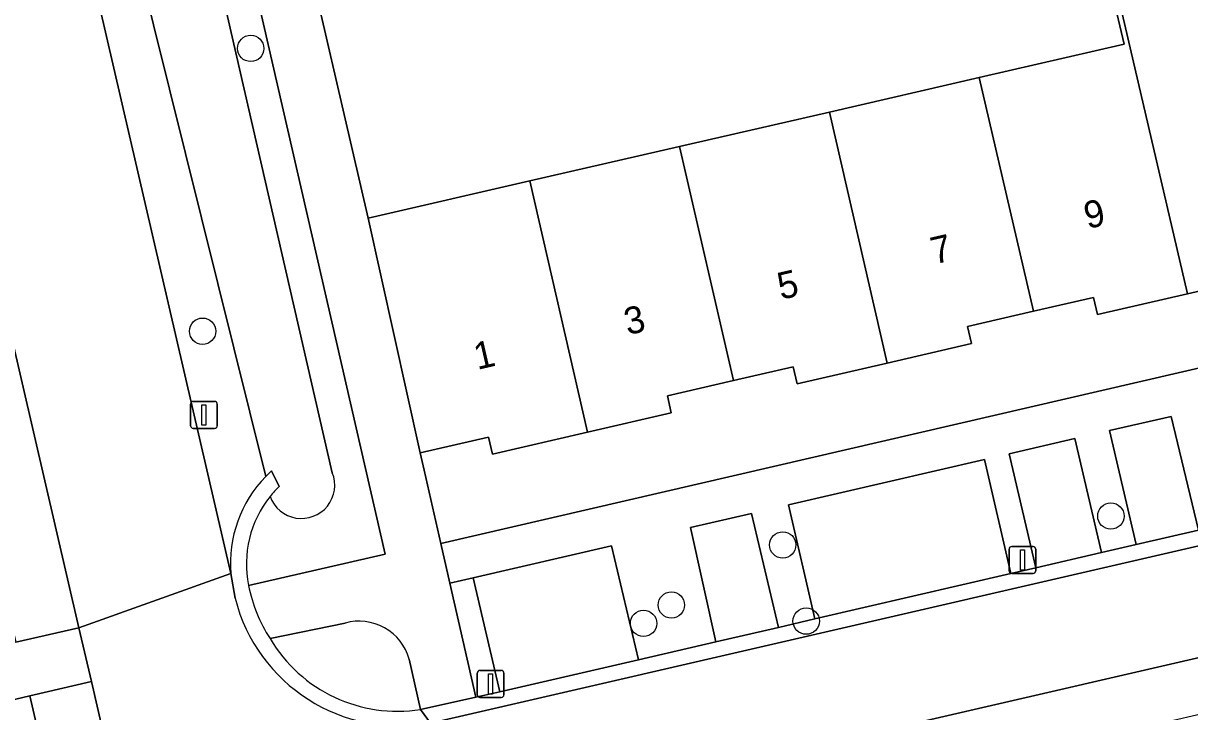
# Model space of a CAD drawing. Extents: x 156412 to 157779, y 382335 to 383768.
# Drawn here: x 156728.86 to 156772.11, y 382632.44 to 382657.96 of the extents above; entities that cross this region are included whole.
import ezdxf

# ---------------------------------------------------------------- set-up
doc = ezdxf.new("R2010")
doc.units = 0
for name, color, linetype in [('IMGEO_Berm_groen', 7, 'Continuous'), ('IMGEO_Boom', 7, 'Continuous'), ('IMGEO_Erf', 7, 'Continuous'), ('IMGEO_Greppel_droge_sloot', 7, 'Continuous'), ('IMGEO_Lichtmast', 7, 'Continuous'), ('IMGEO_Muur', 7, 'Continuous'), ('IMGEO_Pand', 7, 'Continuous'), ('IMGEO_Pand_nummerreeks', 7, 'Continuous'), ('IMGEO_Parkeervlak_halfverhard', 7, 'Continuous'), ('IMGEO_Parkeervlak_open', 7, 'Continuous'), ('IMGEO_Rijbaan_lokaal_gesloten', 7, 'Continuous'), ('IMGEO_Rijbaan_lokaal_open', 7, 'Continuous'), ('IMGEO_Voetpad_open', 7, 'Continuous')]:
    doc.layers.add(name, color=color, linetype=linetype)

msp = doc.modelspace()

# ---------------------------------------------------------------- linework, layer by layer
at = {"layer": 'IMGEO_Berm_groen'}
for points in [[(156737.216, 382637.122), (156742.279, 382638.288), (156737.212, 382660.364), (156736.732, 382660.236), (156734.423, 382669.916), (156734.988, 382670.057), (156729.8, 382692.978)], [(156725, 382688.405), (156725.228, 382687.423), (156725.004, 382687.432), (156736.553, 382637.563)], [(156729.729, 382687.434), (156740.319, 382641.302)], [(156737.852, 382641.163), (156726.53, 382686.636)], [(156740.791, 382635.724), (156738.015, 382635.156)], [(156743.594, 382632.529), (156743.168, 382634.389)]]:
    msp.add_lwpolyline(points, dxfattribs=at)
msp.add_lwpolyline([(156729.11, 382633.03), (156727.486, 382632.653), (156728.727, 382627.263), (156729.855, 382622.503), (156731.463, 382622.867)], close=True, dxfattribs=at)
for centre, radius, start, end in [((156739.176, 382640.838), 1.233, 199.5508, 22.1105), ((156741.202, 382637.92), 4.663, 135.9305, 184.3872), ((156741.125, 382637.925), 3.991, 141.2226, 191.6128), ((156741.32, 382633.882), 1.917, 15.3465, 106.0135), ((156742.728, 382637.928), 5.468, 210.4626, 279.1085)]:
    msp.add_arc(centre, radius, start, end, dxfattribs=at)
at = {"layer": 'IMGEO_Boom'}
for centre in [(156737.294, 382657.033), (156735.511, 382646.547), (156769.189, 382639.696), (156757.019, 382638.624), (156752.891, 382636.398), (156751.86, 382635.718), (156757.89, 382635.8)]:
    msp.add_circle(centre, 0.489, dxfattribs=at)
at = {"layer": 'IMGEO_Erf'}
for points in [[(156772.904, 382670.28), (156767.051, 382668.929), (156761.489, 382667.646), (156755.937, 382666.364), (156750.387, 382665.083), (156744.834, 382663.802), (156738.947, 382662.443), (156741.655, 382650.741), (156747.644, 382652.119), (156753.19, 382653.394), (156758.75, 382654.673), (156764.305, 382655.951), (156769.678, 382657.187), (156769.251, 382659.037), (156769.436, 382659.08), (156775.298, 382660.433)], [(156775.457, 382648.727), (156772.025, 382647.935), (156768.695, 382647.166), (156768.549, 382647.8), (156766.324, 382647.287), (156763.872, 382646.721), (156764.018, 382646.087), (156760.898, 382645.367), (156757.558, 382644.596), (156757.412, 382645.23), (156755.197, 382644.719), (156752.744, 382644.153), (156752.89, 382643.519), (156749.781, 382642.801), (156746.254, 382641.987), (156746.108, 382642.621), (156743.579, 382642.037), (156743.72, 382641.402), (156744.349, 382638.681), (156812.536, 382654.456)]]:
    msp.add_lwpolyline(points, dxfattribs=at)
at = {"layer": 'IMGEO_Greppel_droge_sloot'}
for points in [[(156740.319, 382641.302), (156729.729, 382687.434)], [(156726.53, 382686.636), (156737.852, 382641.163), (156738.07, 382641.375), (156738.348, 382640.791)]]:
    msp.add_lwpolyline(points, dxfattribs=at)
for centre, radius, start, end in [((156739.176, 382640.838), 1.233, 199.5508, 22.1105), ((156741.083, 382637.959), 3.937, 134.0097, 141.2251)]:
    msp.add_arc(centre, radius, start, end, dxfattribs=at)
at = {"layer": 'IMGEO_Lichtmast'}
for p, q in [((156735.165, 382643.946), (156735.955, 382643.946)), ((156735.955, 382643.946), (156735.165, 382643.946)), ((156735.065, 382643.046), (156735.065, 382643.846)), ((156735.065, 382643.846), (156735.065, 382643.046)), ((156736.055, 382643.846), (156736.055, 382643.046)), ((156736.055, 382643.046), (156736.055, 382643.846)), ((156735.955, 382642.946), (156735.165, 382642.946)), ((156735.165, 382642.946), (156735.955, 382642.946)), ((156765.412, 382637.667), (156765.412, 382638.467)), ((156765.412, 382638.467), (156765.412, 382637.667)), ((156765.512, 382638.567), (156766.302, 382638.567)), ((156766.302, 382638.567), (156765.512, 382638.567)), ((156766.402, 382638.467), (156766.402, 382637.667)), ((156766.402, 382637.667), (156766.402, 382638.467)), ((156766.302, 382637.567), (156765.512, 382637.567)), ((156765.512, 382637.567), (156766.302, 382637.567)), ((156745.795, 382633.972), (156746.585, 382633.972)), ((156746.585, 382633.972), (156745.795, 382633.972)), ((156745.695, 382633.072), (156745.695, 382633.872)), ((156745.695, 382633.872), (156745.695, 382633.072)), ((156746.685, 382633.872), (156746.685, 382633.072)), ((156746.685, 382633.072), (156746.685, 382633.872)), ((156746.585, 382632.972), (156745.795, 382632.972)), ((156745.795, 382632.972), (156746.585, 382632.972))]:
    msp.add_line(p, q, dxfattribs=at)
for points in [[(156735.485, 382643.821), (156735.635, 382643.821), (156735.635, 382643.071), (156735.485, 382643.071), (156735.485, 382643.821)], [(156765.832, 382638.442), (156765.982, 382638.442), (156765.982, 382637.692), (156765.832, 382637.692), (156765.832, 382638.442)], [(156746.115, 382633.847), (156746.265, 382633.847), (156746.265, 382633.097), (156746.115, 382633.097), (156746.115, 382633.847)]]:
    msp.add_lwpolyline(points, dxfattribs=at)
for centre, start, end in [((156735.165, 382643.846), 90, 180), ((156735.165, 382643.846), 90, 180), ((156735.955, 382643.846), 0, 90), ((156735.955, 382643.846), 360, 90), ((156735.165, 382643.046), 180, 270), ((156735.165, 382643.046), 180, 270), ((156735.955, 382643.046), 270, 0), ((156735.955, 382643.046), 270, 0), ((156765.512, 382638.467), 90, 180), ((156765.512, 382638.467), 90, 180), ((156766.302, 382638.467), 0, 90), ((156766.302, 382638.467), 360, 90), ((156765.512, 382637.667), 180, 270), ((156765.512, 382637.667), 180, 270), ((156766.302, 382637.667), 270, 0), ((156766.302, 382637.667), 270, 0), ((156745.795, 382633.872), 90, 180), ((156745.795, 382633.872), 90, 180), ((156746.585, 382633.872), 0, 90), ((156746.585, 382633.872), 360, 90), ((156745.795, 382633.072), 180, 270), ((156745.795, 382633.072), 180, 270), ((156746.585, 382633.072), 270, 0), ((156746.585, 382633.072), 270, 0)]:
    msp.add_arc(centre, 0.1, start, end, dxfattribs=at)
at = {"layer": 'IMGEO_Muur'}
msp.add_lwpolyline([(156738.947, 382662.443), (156741.655, 382650.741)], dxfattribs=at)
at = {"layer": 'IMGEO_Pand'}
for points in [[(156775.298, 382660.433), (156769.436, 382659.08), (156772.025, 382647.935), (156775.457, 382648.727), (156775.311, 382649.361), (156777.734, 382649.92)], [(156764.305, 382655.951), (156766.324, 382647.287), (156768.549, 382647.8), (156768.695, 382647.166), (156772.025, 382647.935), (156769.436, 382659.08), (156769.251, 382659.037), (156769.678, 382657.187)], [(156764.305, 382655.951), (156758.75, 382654.673), (156760.898, 382645.367), (156764.018, 382646.087), (156763.872, 382646.721), (156766.324, 382647.287)], [(156753.19, 382653.394), (156755.197, 382644.719), (156757.412, 382645.23), (156757.558, 382644.596), (156760.898, 382645.367), (156758.75, 382654.673)], [(156749.781, 382642.801), (156752.89, 382643.519), (156752.744, 382644.153), (156755.197, 382644.719), (156753.19, 382653.394), (156747.644, 382652.119)], [(156749.781, 382642.801), (156747.644, 382652.119), (156741.655, 382650.741), (156743.579, 382642.037), (156746.108, 382642.621), (156746.254, 382641.987)]]:
    msp.add_lwpolyline(points, close=True, dxfattribs=at)
at = {"layer": 'IMGEO_Parkeervlak_halfverhard'}
for points in [[(156727.963, 382648.268), (156725.682, 382647.725), (156728.587, 382635.019), (156730.916, 382635.549)], [(156731.385, 382633.558), (156729.11, 382633.03), (156731.463, 382622.867), (156733.739, 382623.383), (156732.628, 382628.184)]]:
    msp.add_lwpolyline(points, close=True, dxfattribs=at)
at = {"layer": 'IMGEO_Parkeervlak_open'}
for points in [[(156771.418, 382643.391), (156769.132, 382642.863), (156770.12, 382638.636), (156772.432, 382639.171)], [(156767.857, 382642.568), (156765.419, 382642.004), (156766.401, 382637.776), (156768.845, 382638.341)], [(156764.505, 382641.793), (156757.23, 382640.11), (156758.209, 382635.881), (156765.472, 382637.561)], [(156755.866, 382639.795), (156753.603, 382639.271), (156754.539, 382635.032), (156756.864, 382635.57)], [(156750.675, 382638.594), (156745.548, 382637.408), (156746.531, 382633.18), (156751.676, 382634.37)]]:
    msp.add_lwpolyline(points, close=True, dxfattribs=at)
at = {"layer": 'IMGEO_Rijbaan_lokaal_gesloten'}
for points in [[(156719.479, 382684.929), (156720.255, 382681.599), (156723.431, 382667.857), (156724.186, 382664.553), (156727.193, 382651.603), (156727.963, 382648.268), (156730.916, 382635.549), (156736.553, 382637.563), (156725.004, 382687.432)], [(156736.715, 382636.646), (156736.553, 382637.563), (156730.916, 382635.549), (156731.385, 382633.558)], [(156731.385, 382633.558), (156732.628, 382628.184), (156733.739, 382623.383), (156733.827, 382623.004), (156734.534, 382619.97), (156740.236, 382622.783)]]:
    msp.add_lwpolyline(points, dxfattribs=at)
msp.add_lwpolyline([(156819.996, 382645.43), (156855.169, 382653.553), (156854.261, 382657.483), (156850.364, 382656.581), (156818.765, 382649.282), (156745.677, 382632.413), (156743.958, 382632.023), (156744.772, 382628.056), (156746.776, 382628.519)], close=True, dxfattribs=at)
msp.add_arc((156742.801, 382638.196), 6.28, 194.2859, 280.6162, dxfattribs=at)
at = {"layer": 'IMGEO_Rijbaan_lokaal_open'}
for points in [[(156772.432, 382639.171), (156770.12, 382638.636), (156768.845, 382638.341), (156766.401, 382637.776), (156765.472, 382637.561), (156758.209, 382635.881), (156756.864, 382635.57), (156754.539, 382635.032), (156751.676, 382634.37), (156746.531, 382633.18), (156745.644, 382632.975), (156743.594, 382632.529), (156743.958, 382632.023), (156745.677, 382632.413), (156818.765, 382649.282)], [(156738.348, 382640.791), (156738.07, 382641.375), (156737.852, 382641.163)], [(156736.553, 382637.563), (156736.715, 382636.646)], [(156743.958, 382632.023), (156743.594, 382632.529)]]:
    msp.add_lwpolyline(points, dxfattribs=at)
for centre, radius, start, end in [((156741.202, 382637.92), 4.663, 135.9305, 184.3872), ((156741.125, 382637.925), 3.991, 141.2226, 191.6128), ((156741.083, 382637.959), 3.937, 134.0097, 141.2251), ((156742.533, 382638.138), 5.413, 190.8136, 213.421), ((156742.801, 382638.196), 6.28, 194.2859, 280.6162), ((156742.728, 382637.928), 5.468, 210.4626, 279.1085)]:
    msp.add_arc(centre, radius, start, end, dxfattribs=at)
at = {"layer": 'IMGEO_Voetpad_open'}
for points in [[(156743.72, 382641.402), (156743.579, 382642.037), (156741.655, 382650.741), (156738.947, 382662.443), (156738.431, 382664.674), (156738.106, 382666.084), (156737.588, 382668.326), (156735.532, 382677.202), (156735.095, 382679.094), (156733.067, 382687.87), (156731.555, 382694.305), (156729.8, 382692.978), (156734.988, 382670.057), (156736.004, 382665.629), (156737.212, 382660.364), (156742.279, 382638.288), (156737.216, 382637.122)], [(156812.536, 382654.456), (156744.349, 382638.681), (156744.681, 382637.208), (156745.548, 382637.408), (156750.675, 382638.594), (156751.676, 382634.37), (156754.539, 382635.032), (156753.603, 382639.271), (156755.866, 382639.795), (156756.864, 382635.57), (156758.209, 382635.881), (156757.23, 382640.11), (156764.505, 382641.793), (156765.472, 382637.561), (156766.401, 382637.776), (156765.419, 382642.004), (156767.857, 382642.568), (156768.845, 382638.341), (156770.12, 382638.636), (156769.132, 382642.863), (156771.418, 382643.391), (156772.432, 382639.171)], [(156743.168, 382634.389), (156743.594, 382632.529), (156745.644, 382632.975), (156744.681, 382637.208), (156744.349, 382638.681), (156743.72, 382641.402)], [(156738.015, 382635.156), (156740.791, 382635.724)]]:
    msp.add_lwpolyline(points, dxfattribs=at)
for points in [[(156817.808, 382642.832), (156820.465, 382643.445), (156819.996, 382645.43), (156746.776, 382628.519), (156747.237, 382626.524)], [(156745.548, 382637.408), (156744.681, 382637.208), (156745.644, 382632.975), (156746.531, 382633.18)], [(156730.916, 382635.549), (156728.587, 382635.019), (156727.027, 382634.664), (156727.486, 382632.653), (156729.11, 382633.03), (156731.385, 382633.558)]]:
    msp.add_lwpolyline(points, close=True, dxfattribs=at)
for centre, radius, start, end in [((156742.533, 382638.138), 5.413, 190.8136, 213.421), ((156741.32, 382633.882), 1.917, 15.3465, 106.0135)]:
    msp.add_arc(centre, radius, start, end, dxfattribs=at)

# ---------------------------------------------------------------- texts
at = {"layer": 'IMGEO_Pand_nummerreeks'}
for s, p in [('9', (156768.32, 382650.334)), ('7', (156762.637, 382649.022)), ('5', (156756.953, 382647.71)), ('3', (156751.269, 382646.398)), ('1', (156745.697, 382645.112))]:
    msp.add_text(s, height=1, rotation=12.9959, dxfattribs=at).set_placement(p)

doc.saveas('drawing.dxf')
